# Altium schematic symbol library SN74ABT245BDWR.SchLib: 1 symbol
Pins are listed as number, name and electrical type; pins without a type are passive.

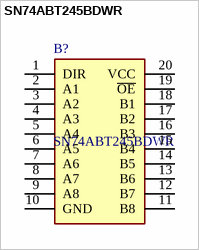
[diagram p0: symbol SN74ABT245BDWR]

## SN74ABT245BDWR
designator B?
Texas Instruments SN74ABT245BDWR, Bus Transceiver, 8-Bit Non-Inverting TTL, 5V, 20-Pin SOIC; Geometry.Height: 2.65mm
footprint SOIC127P1030X265-20N
pins: 1 DIR, 2 A1, 3 A2, 4 A3, 5 A4, 6 A5, 7 A6, 8 A7, 9 A8, 10 GND, 11 B8, 12 B7, 13 B6, 14 B5, 15 B4, 16 B3, 17 B2, 18 B1, 19 ~{OE}, 20 VCC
